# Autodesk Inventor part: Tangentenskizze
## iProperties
Created: 2005-06
Part Number: Tangentenskizze
Cost Center: 0 kg
Document SubType Name: Modeling
Designer: thomas
Manufacturer: Standard
Standards Organization: Custom
Author: thomas
SaveDate: 2005-06-21
SaveTime: 15:07
TotalMass: 0 kg
